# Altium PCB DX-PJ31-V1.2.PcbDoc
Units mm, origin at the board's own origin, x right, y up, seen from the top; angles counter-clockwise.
Board outline 28 x 32 mm, 2 copper layers (Top, Bottom), stack 0.324 mm thick; 82 components, 60 nets, 437 pads, 151 vias.
Unrouted connection lines stored in the file: 298.
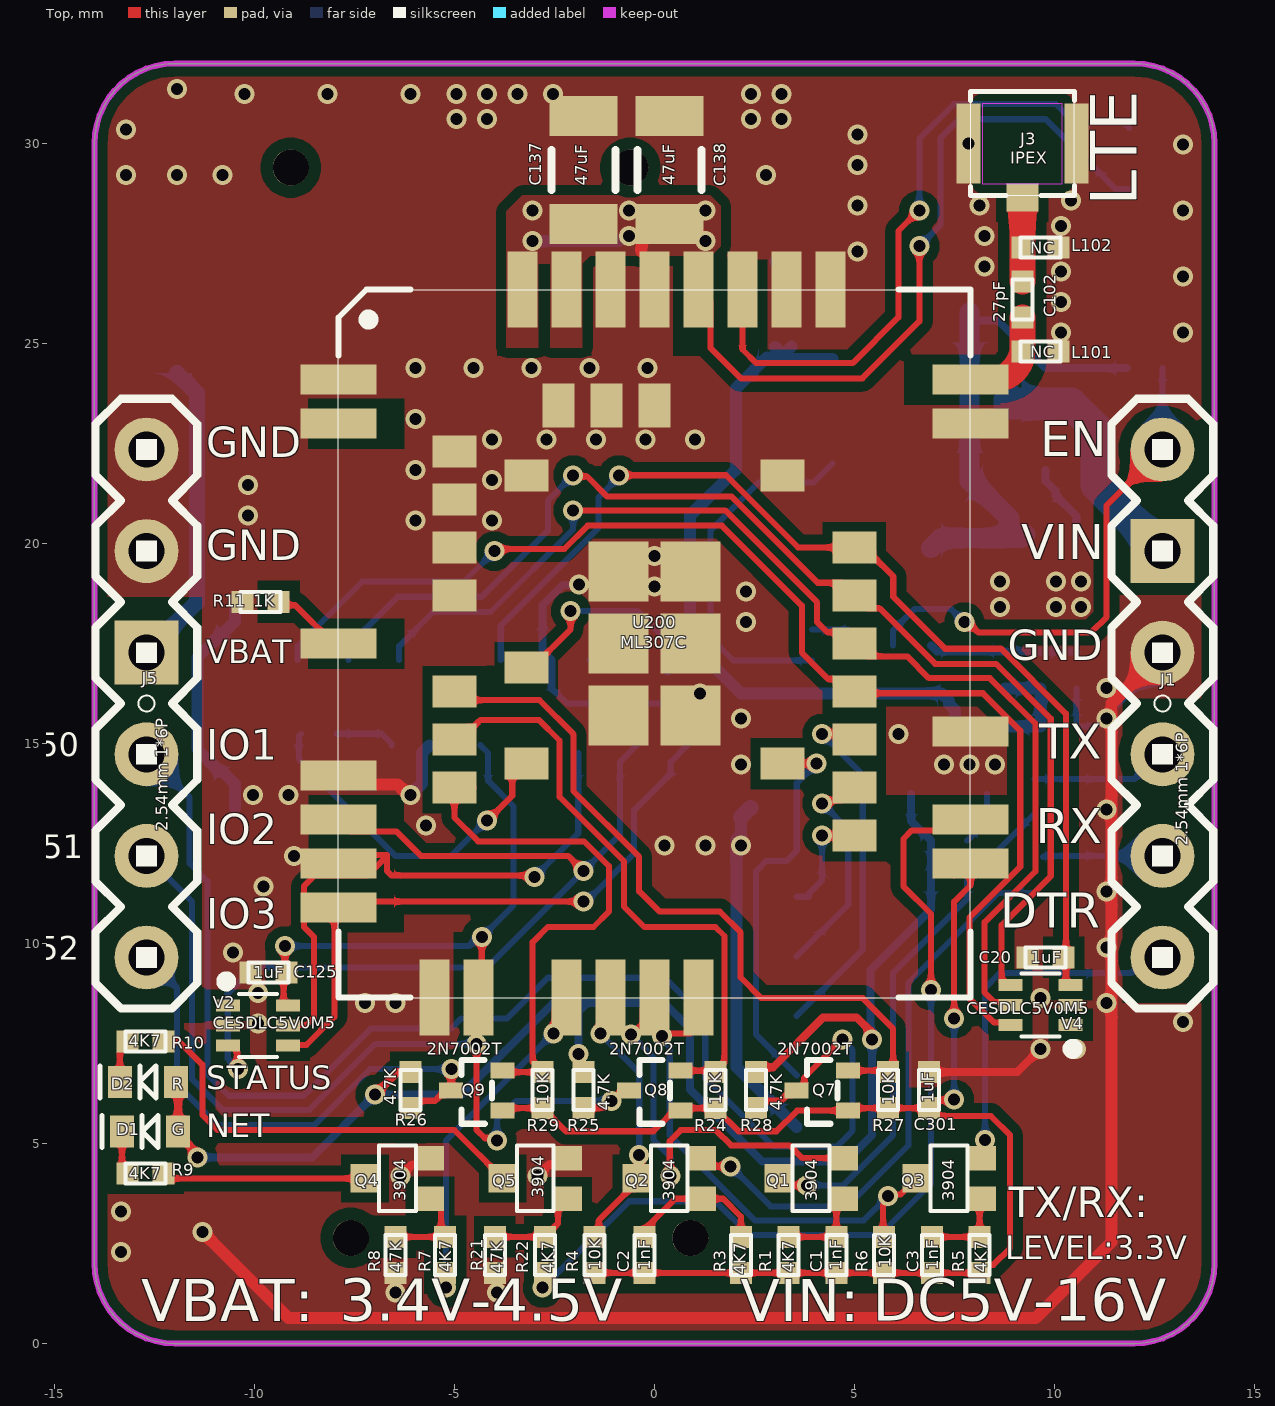
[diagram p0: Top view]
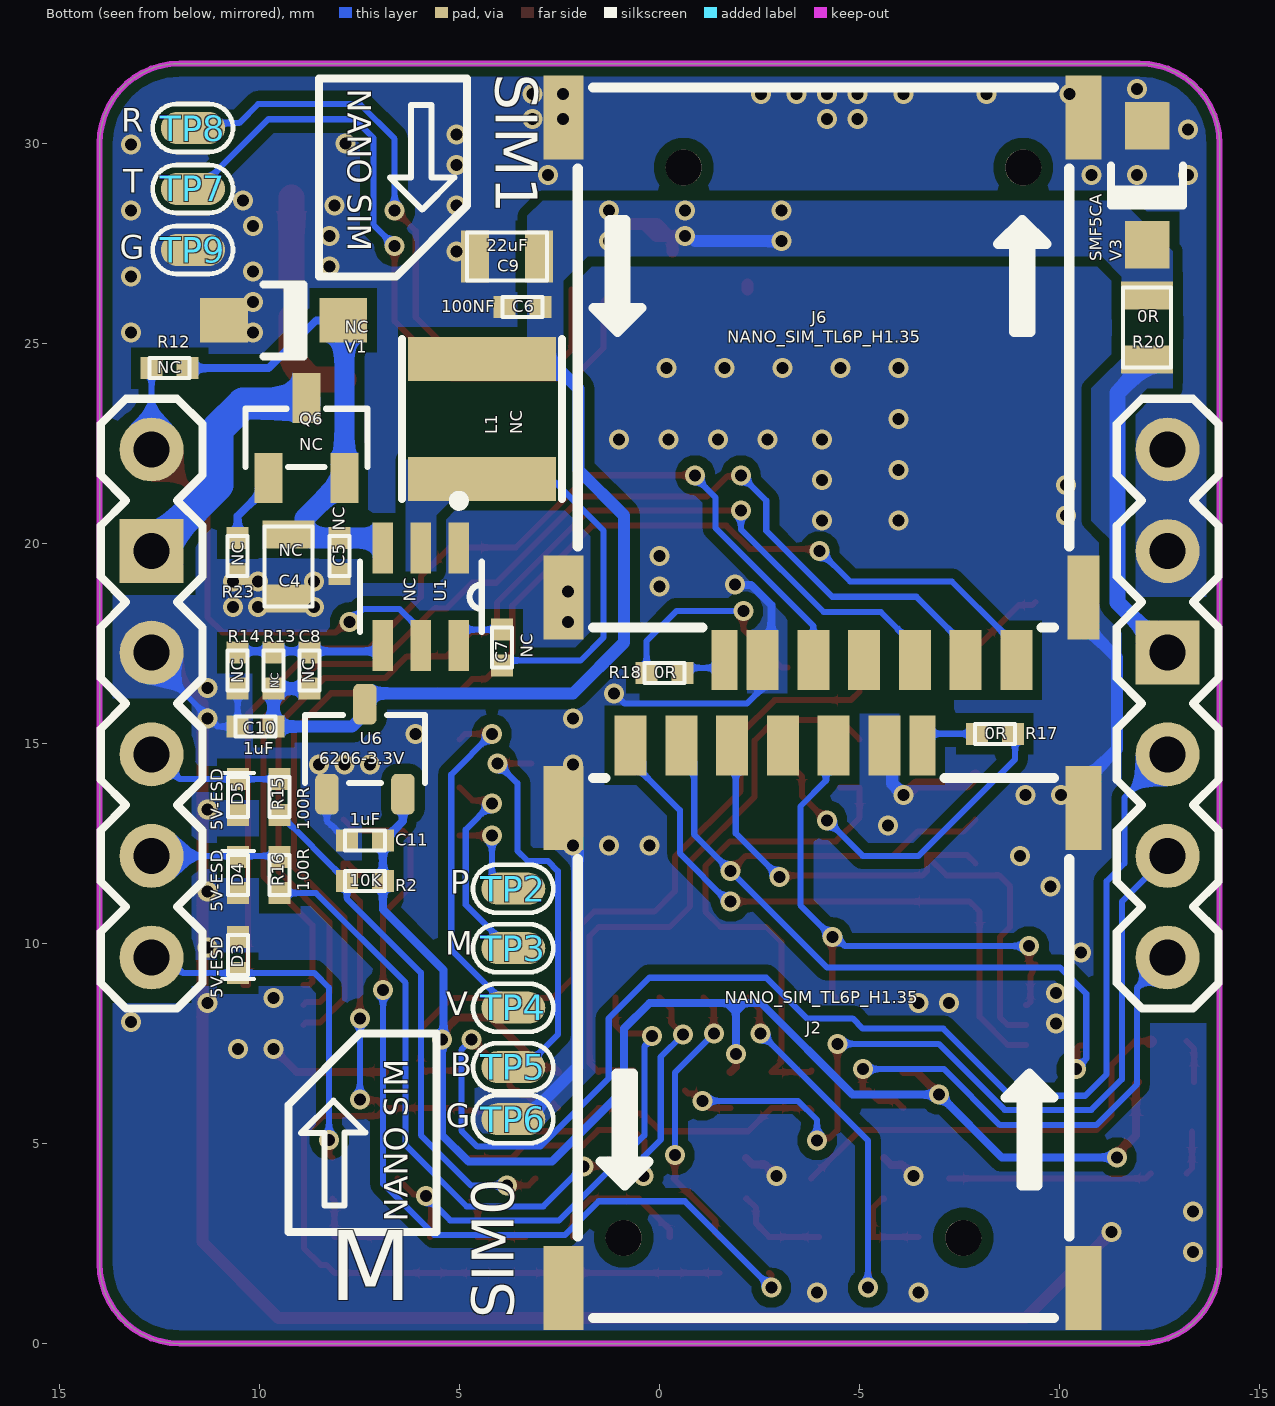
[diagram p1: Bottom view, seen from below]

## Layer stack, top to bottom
Solder Mask Top: solder mask 0.0102, Solder Resist, Dk 3.5
Top: signal copper 0.035
Dielectric1: dielectric 0.254, FR-4, Dk 4.8
Bottom: signal copper 0.035
Solder Mask Bottom: solder mask 0.0102, Solder Resist, Dk 3.5

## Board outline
-14,2 -14,30 cw(c-12,30) -12,32 12,32 cw(c12,30) 14,30 14,2 cw(c12,2) 12,0 -12,0 cw(c-12,2)

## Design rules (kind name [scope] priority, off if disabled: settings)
Clearance [All] p1: gap=0.2 ignorepadtopadclearanceinfootprint=TRUE except(0: Arc-Hole Track-Hole SMDPad-Hole THPad-Hole Via-Hole Fill-Hole Poly-Hole Region-Hole Text-Hole; 0.25: Arc-Fill Arc-Poly Arc-Region Track-Fill Track-Poly Track-Region SMDPad-Fill SMDPad-Poly SMDPad-Region Via-Fill Via-Poly Via-Region Fill-Fill Fill-Poly Fill-Region Poly-Poly Poly-Region Region-Region; 0.3: THPad-Fill THPad-Poly THPad-Region)
ComponentClearance "ComponentClearance - Default - DEFAULT" [All] p1: gap=0.152 collisioncheckmode=3 verticalgap=0.254 showdistances=FALSE
FanoutControl Fanout_SOIC [IsSOIC] p1: bgadir=Out bgaviamode=Centered fanoutstyle=Auto fanoutdirection=Alternating viagrid=0.025 // Fanout_SOIC (Default Rule)
FanoutControl Fanout_Small [(CompPinCount < 5)] p2: bgadir=Out bgaviamode=Centered fanoutstyle=Auto fanoutdirection=OutThenIn viagrid=0.025 // Fanout_Small (Default Rule)
FanoutControl Fanout_LCC [IsLCC] p3: bgadir=Out bgaviamode=Centered fanoutstyle=Auto fanoutdirection=Alternating viagrid=0.025 // Fanout_LCC (Default Rule)
FanoutControl Fanout_BGA [IsBGA] p4: bgadir=Out bgaviamode=Centered fanoutstyle=Auto fanoutdirection=Alternating viagrid=0.025 // Fanout_BGA (Default Rule)
HoleToHoleClearance "HoleToHoleClearance - Default - DEFAULT" [All] p1: gap=0.152 allowstackedmicrovias=TRUE
Length "Default Length" [All] p1: maxlimit=1270 minlimit=0
MaxMinImpedance "Default Impedance" [All] p1: minimum=50.00 maximum=150.0
MinimumSolderMaskSliver [All] p1: minsoldermaskwidth=0.2
ParallelSegment "Default Parallel Segment Adjasent" [All] p1: limit=25.4 gap=5.08
ParallelSegment "Default Parallel Segment Same Layer" [All] p2: limit=25.4 gap=5.08
PlaneClearance "PlaneClearance - FootPrint 'LUOSI2MM-P'" [HasFootprint('LUOSI2MM-P')] p1: clearance=1.075 // PAD - Power Plane Clearance
PlaneConnect "PlaneConnect - FootPrint 'LUOSI2MM-NP'" [All] p1: planeconnectstyle=Direct reliefexpansion=1.675 reliefentries=4 reliefconductorwidth=0.55 reliefairgap=0
PolygonConnect "PolygonConnect - FootPrint 'LUOSI2MM-NP'" [All] p1: connectstyle=Direct reliefconductorwidth=0.55 reliefentries=4 polygonreliefangle="45 Angle" airgapwidth=0.254
RoutingLayers "RoutingLayers - Default - DEFAULT" [All] p1: top layer_v5=TRUE bottom layer_v5=TRUE
RoutingPriority "RoutingPriority - Default - DEFAULT" [All] p1: routingpriority=3
RoutingTopology "Default Routing Topology" [All] p1: topology=Shortest
RoutingVias "RoutingVias - Default - DEFAULT" [All] p1: holewidth=0.3 width=0.5 viastyle="Through Hole" minholewidth=0.25 minwidth=0.45 maxholewidth=1 maxwidth=2
SMDToCorner "SMDToCorner - Default - DEFAULT" [All] p1: distance=60000
SilkToSilkClearance [All] p1: silktosilkclearance=0
SilkToSolderMaskClearance [IsPad] p1: minsilkscreentomaskgap=0 clearancetoexposedcopper=TRUE
SolderMaskExpansion [All] p1: expansion=0.102 istentingtop=FALSE
Width "Default Width" [All] p1: maxlimit=1 minlimit=0.15 preferedwidth=0.15
16 further rules are at their usual default settings.

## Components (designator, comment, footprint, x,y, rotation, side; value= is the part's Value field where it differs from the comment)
C1 "1nF" SMD0402 4.547,2.217 r270 top
C2 "1nF" SMD0402 -0.254,2.217 r270 top
C3 "1nF" SMD0402 6.934,2.217 r270 top
C4 "NC" SMD0805 9.271,19.431 r90 bottom value=10uF
C5 "NC" SMD0402 8.001,19.685 r90 bottom value=0.1uF
C6 "100NF" SMD0402 3.429,25.908 r180 bottom value=1uF
C7 "NC" SMD0402 3.937,17.399 r90 bottom value=0.1uF
C8 "NC" SMD0402 8.758,16.822 r270 bottom value=10pF
C9 "22uF" SMD0805 3.81,27.178 r180 bottom
C10 "1uF" SMD0402 10.096,15.425 r180 bottom
C11 "1uF" SMD0402 7.366,12.573 r180 bottom
C20 "1uF" SMD0402 9.779,9.652 r0 top
C102 "27pF" SMD0402 9.2,26.1 r90 top
C125 "1uF" SMD0402 -9.652,9.271 r0 top
C137 "47uF" C1206L -1.778,29.337 r270 top
C138 "47uF" C1206L 0.381,29.337 r270 top
C301 "1uF" SMD0402 6.858,6.334 r270 top
D1 "G" LED_0603 -12.611,5.3 r180 top
D2 "R" LED_0603 -12.665,6.54 r180 top value=G
D3 "5V-ESD" SMD0402_ESD_TVS 10.541,9.71 r90 bottom value="5V 10P"
D4 "5V-ESD" SMD0402_ESD_TVS 10.541,11.713 r270 bottom value="5V 10P"
D5 "5V-ESD" SMD0402_ESD_TVS 10.541,13.658 r270 bottom value="5V 10P"
J1 "2.54mm 1*6P" 254-6#1 12.7,16 r270 top locked value="2.54mm 1*6P直针/黄色"
J2 "NANO_SIM_TL6P_H1.35" nanosim_#1 -4.619,8.191 r180 bottom locked value="NANO SIM TL6P H1.35"
J3 "IPEX" IPEX 9.2,30 r270 top
J5 "2.54mm 1*6P" 254-6#2 -12.7,16 r270 top locked value="2.54mm 1*6P直针/黄色"
J6 "NANO_SIM_TL6P_H1.35" nanosim_#2 -3.577,23.849 r0 bottom locked value="NANO SIM TL6P H1.35"
L1 "NC" WPN4020H 4.445,23.114 r90 bottom value=WPN4020H2R2MT
L101 "NC" SMD0402 9.65,24.8 r0 top
L102 "NC" SMD0402 9.65,27.4 r0 top
Q1 "3904" EMT3 3.916,4.127 r90 top value=3904/SOT-523
Q2 "3904" EMT3 0.368,4.127 r90 top value=3904/SOT-523
Q3 "3904" EMT3 7.364,4.127 r90 top value=3904/SOT-523
Q4 "3904" EMT3 -6.428,4.127 r90 top value=3904/SOT-523
Q5 "3904" EMT3 -2.98,4.127 r90 top value=3904/SOT-523
Q6 "NC" SOT-23-3_L2.9-W1.3-P1.90-LS2.4-BR 8.829,22.644 r270 bottom
Q7 "2N7002T" SC-75-3_L1.6-W0.8-P1.00-LS1.7-BR 4.199,6.323 r0 top
Q8 "2N7002T" SC-75-3_L1.6-W0.8-P1.00-LS1.7-BR 0.004,6.323 r0 top
Q9 "2N7002T" SC-75-3_L1.6-W0.8-P1.00-LS1.7-BR -4.445,6.323 r0 top
R1 "4K7" SMD0402 3.353,2.217 r90 top
R2 "10K" SMD0402 7.366,11.557 r180 bottom
R3 "4K7" SMD0402 2.159,2.217 r90 top
R4 "10K" SMD0402 -1.499,2.217 r270 top
R5 "4K7" SMD0402 8.128,2.217 r90 top
R6 "10K" SMD0402 5.74,2.217 r270 top
R7 "4K7" SMD0402 -5.232,2.217 r270 top
R8 "47K" SMD0402 -6.477,2.217 r90 top
R9 "4K7" SMD0402 -12.73,4.254 r180 top value=2K2
R10 "4K7" SMD0402 -12.73,7.556 r180 top value=2K2
R11 "1K" SMD0402 -9.848,18.542 r180 top
R12 "NC" SMD0402 12.25,24.384 r0 bottom value=10K
R13 "NC" SMD0402 9.652,16.822 r90 bottom value=41.2K1%
R14 "NC" SMD0402 10.546,16.822 r270 bottom value=10K1%
R15 "100R" SMD0402 9.496,13.658 r270 bottom value=1K
R16 "100R" SMD0402 9.496,11.713 r270 bottom value=1K
R17 "0R" SMD0402 -8.382,15.24 r0 bottom value=1K
R18 "0R" SMD0402 -0.127,16.764 r180 bottom value=1K
R20 "0R" SMD0805 -12.192,25.4 r90 bottom value=1K
R21 "47K" SMD0402 -3.988,2.217 r90 top
R22 "4K7" SMD0402 -2.743,2.217 r270 top
R23 "NC" SMD0402 10.546,19.685 r270 bottom value=1K
R24 "10K" SMD0402 1.524,6.334 r90 top
R25 "4.7K" SMD0402 -1.778,6.334 r270 top value=10K
R26 "4.7K" SMD0402 -6.096,6.334 r270 top value=10K
R27 "10K" SMD0402 5.842,6.334 r270 top value=4K7
R28 "4.7K" SMD0402 2.54,6.334 r90 top value=4K7
R29 "10K" SMD0402 -2.794,6.334 r90 top value=4K7
TP2 "TP2" TP-0.8X1.6 3.656,11.369 r0 bottom value=NC
TP3 "TP3" TP-0.8X1.6 3.656,9.882 r0 bottom value=NC
TP4 "TP4" TP-0.8X1.6 3.656,8.395 r0 bottom value=NC
TP5 "TP5" TP-0.8X1.6 3.656,6.908 r0 bottom value=NC
TP6 "TP6" TP-0.8X1.6 3.656,5.608 r0 bottom value=NC
TP7 "TP7" TP-0.8X1.6 11.665,28.864 r0 bottom value=NC
TP8 "TP8" TP-0.8X1.6 11.665,30.388 r0 bottom value=NC
TP9 "TP9" TP-0.8X1.6 11.665,27.34 r0 bottom value=NC
U1 "NC" DDC0006A_L 5.969,18.669 r270 bottom value=TPS563201DDCR
U6 "6206-3.3V" SOT23-3P95_280X110L60X40L 7.366,14.859 r180 bottom
U200 "ML307C" L511-1 0,17.5 r0 top locked value=L511
V1 "NC" SOD123FL 9.398,25.581 r0 bottom value=SMF18CA/SOD-123FL
V2 "CESDLC5V0M5" SOT-563_L1.6-W1.2-P0.50-LS1.6-BR -9.906,7.954 r180 top
V3 "SMF5CA" SOD123FL -12.192,28.956 r90 bottom value=SMF18CA/SOD-123FL
V4 "CESDLC5V0M5" SOT-563_L1.6-W1.2-P0.50-LS1.6-BR 9.652,8.466 r0 top

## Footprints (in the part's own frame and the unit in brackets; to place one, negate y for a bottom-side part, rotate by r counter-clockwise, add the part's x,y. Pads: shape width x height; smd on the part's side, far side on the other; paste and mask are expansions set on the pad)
254-6#1 [mm]
  round 1.6 hole 0.9: 1(6.35,0) 2(3.81,0) 3(1.27,0) 4(-1.27,0) 6(-6.35,0)
  rect 1.6x1.6 hole 0.9: 5(-3.81,0)
  silkscreen extent -7.62,-1.27 7.62,1.27
254-6#2 [mm]
  round 1.6 hole 0.9: 1(6.35,0) 2(3.81,0) 3(1.27,0) 5(-3.81,0) 6(-6.35,0)
  rect 1.6x1.6 hole 0.9: 4(-1.27,0)
  silkscreen extent -7.62,-1.27 7.62,1.27
C1206L [mm]
  rect 1x1.7 smd: 1(-1.35,0) 2(1.35,0)
  silkscreen extent -0.5,-0.8 0.5,0.8
DDC0006A_L [mil]
  rect 50x20 smd mask+2.01: 1(-47.99,37.4) 2(-47.99,0) 3(-47.99,-37.4) 4(47.99,-37.4) 5(47.99,0) 6(47.99,37.4)
  silkscreen extent -99,-60 34,60
EMT3 [mil]
  rect 24x28 smd: 1(20,-32) 2(-20,-32)
  rect 28x28 smd: 3(0,32)
  silkscreen extent -32,-18 32,18
IPEX [mm]
  rect 2x0.6 smd mask+0.05: 1(0,1.35) 2(0,-1.35)
  rect 0.7x0.8 smd mask+0.025: 3(1.35,0)
  silkscreen extent -1.3,-1.3 1.3,1.3
L511-1 [mm]
  rect 1.9x0.75 on Top Solder: 1(-7.9,-6.6) 1(-7.9,-5.5) 1(-7.9,-4.4) 1(-7.9,-3.3) 1(-7.9,0) 1(-7.9,5.5) 1(-7.9,6.6) 1(7.9,-5.5) 1(7.9,-4.4) 1(7.9,-2.2) 1(7.9,5.5) 1(7.9,6.6)
  rect 1.9x0.75 smd: 1(-7.9,6.6) 2(-7.9,5.5) 7(-7.9,0) 10(-7.9,-3.3) 11(-7.9,-4.4) 12(-7.9,-5.5) 13(-7.9,-6.6) 24(7.9,-5.5) 25(7.9,-4.4) 27(7.9,-2.2) 34(7.9,5.5) 35(7.9,6.6)
  rect 0.75x1.9 on Top Solder: 1(-5.5,-8.85) 1(-4.4,-8.85) 1(-3.3,8.85) 1(-2.2,-8.85) 1(-2.2,8.85) 1(-1.1,-8.85) 1(-1.1,8.85) 1(0,-8.85) 1(0,8.85) 1(1.1,-8.85) 1(3.3,8.85) 1(4.4,8.85) 40(2.2,8.85) 41(1.1,8.85)
  rect 1.9x0.75 on Top Overlay: 2(-7.9,-2.2) 2(-7.9,-1.1) 2(-7.9,1.1) 2(-7.9,2.2) 2(-7.9,3.3) 2(-7.9,4.4) 2(-7.9,4.4) 14(7.9,-6.6) 14(7.9,-3.3) 14(7.9,-1.1) 14(7.9,0) 14(7.9,1.1) 14(7.9,2.2) 14(7.9,3.3) 14(7.9,4.4)
  round 0 all layers, no hole: 3(0,0) 4(0,0) 5(0,0) 6(0,0) 8(0,0) 9(0,0) 15(0,0) 20(0,0) 21(0,0) 22(0,0) 23(0,0) 25(0,0) 26(0,0) 28(0,0) 29(0,0) 31(0,0) 32(0,0) 33(0,0) 38(0,0) 39(0,0) 44(0,0) 49(0,0) 50(0,0) 51(0,0) 52(0,0) 53(0,0) 54(0,0) 55(0,0) 56(0,0) 57(0,0) 58(0,0) 62(0,0) 63(0,0) 64(0,0) 65(0,0) 66(0,0) 67(0,0) 68(0,0) 69(0,0) 74(0,0) 75(0,0) 76(0,0) 77(0,0) 78(0,0) 79(0,0) 80(0,0) 81(0,0) 83(0,0) 84(0,0) 85(0,0) 86(0,0) 87(0,0) 96(0,0) 97(0,0) 98(0,0) 99(0,0) 100(0,0) 101(0,0) 102(0,0) 103(0,0) 104(0,0) 105(0,0) 106(0,0) 107(0,0) 108(0,0) 109(0,0)
  rect 0.75x1.9 on Top Overlay: 14(-5.5,8.85) 14(-4.4,8.85) 14(-3.3,-8.85) 14(2.2,-8.85) 14(3.3,-8.85) 14(4.4,-8.85) 14(5.5,-8.85) 14(5.5,8.85)
  rect 0.75x1.9 smd: 14(-4.4,-8.85) 16(-2.2,-8.85) 17(-1.1,-8.85) 18(0,-8.85) 19(1.1,-8.85) 36(4.4,8.85) 37(3.3,8.85) 38(2.2,8.85) 39(1.1,8.85) 40(0,8.85) 41(-1.1,8.85) 42(-2.2,8.85) 43(-3.3,8.85) 95(-5.5,-8.85)
  rect 1.1x0.8 on Top Overlay: 45(-5,-6) 45(-5,-4.8) 45(-5,0) 45(-5,6) 45(5,-6) 45(5,3.6) 45(5,4.8) 45(5,6) 70(-3.2,1.8) 70(3.2,-0.6) 70(3.2,1.8) 71(-3.2,-4.2) 71(-3.2,-1.8) 71(-3.2,0.6) 71(-3.2,3) 71(3.2,-4.2) 71(3.2,-1.8) 71(3.2,0.6) 71(3.2,3)
  rect 1.1x0.8 on Top Solder: 45(-5,-3.6) 45(-5,-2.4) 45(-5,-1.2) 45(-5,1.2) 45(-5,2.4) 45(-5,3.6) 45(-5,4.8) 45(-3.2,-3) 45(-3.2,-0.6) 45(-3.2,4.2) 45(3.2,-3) 45(3.2,4.2) 45(5,-4.8) 45(5,-3.6) 45(5,-2.4) 45(5,-1.2) 45(5,0) 45(5,1.2) 45(5,2.4)
  rect 1.1x0.8 smd: 45(-5,4.8) 46(-5,3.6) 47(-5,2.4) 48(-5,1.2) 50(-5,-1.2) 51(-5,-2.4) 52(-5,-3.6) 59(5,-4.8) 60(5,-3.6) 61(5,-2.4) 62(5,-1.2) 63(5,0) 64(5,1.2) 65(5,2.4) 73(-3.2,4.2) 77(-3.2,-0.6) 79(-3.2,-3) 82(3.2,-3) 88(3.2,4.2)
  rect 0.8x1.1 on Top Overlay: 45(-3.6,-6.05) 45(-3.6,5.95) 70(0,-6.05) 70(0,-4.05) 70(2.4,-6.05) 70(2.4,5.95) 71(-1.2,-6.05) 71(-1.2,-4.05) 71(1.2,-6.05) 71(1.2,-4.05) 71(1.2,5.95) 72(-2.4,-6.05) 72(3.6,-6.05) 72(3.6,5.95)
  rect 0.8x1.1 on Top Solder: 45(-2.4,5.95) 45(-1.2,5.95) 45(0,5.95)
  rect 0.8x1.1 smd: 70(0,5.95) 71(-1.2,5.95) 72(-2.4,5.95)
  rect 1.5x1.5 on Top Solder: 89(-0.9,-1.8) 89(-0.9,0) 89(-0.9,1.8) 89(0.9,-1.8) 89(0.9,0) 89(0.9,1.8)
  rect 1.5x1.5 smd: 89(-0.9,1.8) 90(-0.9,0) 91(-0.9,-1.8) 92(0.9,-1.8) 93(0.9,0) 94(0.9,1.8)
  silkscreen extent -7.9,-8.85 7.9,8.85
LED_0603 [mm]
  rect 0.6x0.8 smd: 1(-0.7,0) 2(0.7,0)
  silkscreen extent -0.2,-0.4 1.2,0.4
nanosim_#1 [mm]
  rect 1x2.1 smd: 8(-7.016,5.2) 9(-7.016,-6.8)
  rect 0.9x2.1 smd: 8(5.974,5.2) 9(5.974,-6.8)
  rect 0.8x1.5 smd: C1(-0.266,6.765) C2(-2.806,6.765) C3(-5.346,6.765) C5(1.004,6.765) C6(-1.536,6.765) C7(-4.076,6.765)
  rect 0.65x1.5 smd: CD(1.954,6.765)
  round 0.9 hole 0.9 unplated: ""(-5.516,-5.551) ""(2.974,-5.551)
  silkscreen extent -6.67,-7.55 5.62,5.95
nanosim_#2 [mm]
  rect 0.8x2.1 smd: 8(-7.016,5.2)
  rect 1x2.1 smd: 8(5.974,5.2) 9(5.974,-6.8)
  rect 0.9x2.1 smd: 9(-7.016,-6.8)
  rect 0.8x1.5 smd: C1(-0.266,6.765) C2(-2.806,6.765) C3(-5.346,6.765) C5(1.004,6.765) C6(-1.536,6.765) C7(-4.076,6.765)
  rect 0.65x1.5 smd: CD(1.954,6.765)
  round 0.9 hole 0.9 unplated: ""(-5.516,-5.551) ""(2.974,-5.551)
  silkscreen extent -6.67,-7.55 5.62,5.95
SC-75-3_L1.6-W0.8-P1.00-LS1.7-BR [mm]
  rect 0.6x0.4 smd paste+0.051: 1(0.643,-0.5) 2(0.643,0.5) 3(-0.643,0)
  silkscreen extent -0.38,-0.83 0.38,0.76
SMD0402 [mm]
  rect 0.55x0.55 smd: 1(-0.45,0) 2(0.45,0)
  silkscreen extent -0.5,-0.25 0.5,0.25
SMD0402_ESD_TVS [mm]
  rect 0.55x0.55 smd: 1(-0.45,0) 2(0.45,0)
  silkscreen extent -0.6,-0.4 0.5,0.4
SMD0805 [mm]
  rect 0.7x1.3 smd: 1(-0.8,0) 2(0.8,0)
  silkscreen extent -1,-0.6 1,0.6
SOD123FL [mm]
  rect 1.19x1.12 smd: 1(-1.49,0) 2(1.49,0)
  silkscreen extent -0.5,-0.9 0.5,0.9
SOT23-3P95_280X110L60X40L [mm]
  rrect50% 0.589x1.02 smd: 1(-0.95,-1.125) 2(0.95,-1.125) 3(0,1.125)
  silkscreen extent -1.5,-0.85 1.5,0.85
SOT-23-3_L2.9-W1.3-P1.90-LS2.4-BR [mm]
  rect 1.25x0.7 smd: 1(1,-0.95) 2(1,0.95) 3(-1,0)
  silkscreen extent -0.73,-1.53 0.73,1.53
SOT-563_L1.6-W1.2-P0.50-LS1.6-BR [mm]
  rect 0.6x0.3 smd: 1(0.75,-0.5) 2(0.75,0) 3(0.75,0.5) 4(-0.75,0.5) 5(-0.75,0) 6(-0.75,-0.5)
  silkscreen extent -0.48,-1.22 0.92,0.79
TP-0.8X1.6 [mm]
  oval 1.6x0.8 smd paste-0.8 mask+0.05: 1(0,0)
  silkscreen extent -1,-0.6 1.01,0.6
WPN4020H [mm]
  rect 1.1x3.7 smd: 1(-1.5,0) 2(1.5,0)
  silkscreen extent -2,-2 2,2

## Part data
C1 C2 C3 C5 C6 C7 C8 C10 C11 C20 C102 C125 C301: library part CAP-0402, PART NUMBER=0402ZG104Z, Tolerance=+/-5%
C4 C9 C137 C138: library part CAP-0805
D1 D2: library part LED_0603
D3 D4 D5 V1 V3: library part ESD-TVS-0402
J1 J5: library part 254-6
J2 J6: JLCPCB_Part_Class="Extended Part", Manufacturer_Part="NANO SIM TL6P H1.35"
J3: library part UFLR_0
L1: library part INCT_1_L5
L101 L102: library part IND-0402
Q1 Q2 Q3 Q4 Q5: library part DTC123JETL
Q6: library part MOS-P, "1:G 2:D 3:S"
R1 R2 R3 R4 R5 R6 R7 R8 R9 R10 R11 R12 R13 R14 R15 R16 R17 R18 R20 R21 R22 R23 R24 R25 R26 R27 R28 R29: library part RES-0402
TP2 TP3 TP4 TP5 TP6 TP7 TP8 TP9: library part TP_C150A, "test point on module"
U1: library part TPS563201DDCR, Mfr_Name="Texas Instruments"
U6: library part LDO
U200: library part L511_BLGA
V2 V4: Breakdown_Voltage=6.2V, JLCPCB_Part_Class="Extended Part", Maximum_Clamping_Voltage=13V, Peak_Pulse_Current_(Ipp)@10/1000us=2.5A, Reverse_Stand_Off_Voltage_(Vrwm)=5V

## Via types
v1: diameter 0.5, hole 0.3, Top to Bottom, tented both sides, 151 vias

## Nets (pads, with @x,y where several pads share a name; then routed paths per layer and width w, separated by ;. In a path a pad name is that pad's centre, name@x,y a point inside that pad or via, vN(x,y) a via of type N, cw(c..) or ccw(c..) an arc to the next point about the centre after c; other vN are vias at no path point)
ANT_RF: C102.1 L101.1 U200.35 | length 2.5
  Top w0.646: U200.35 8.5,24.1 ccw(c8.5,24.8) L101.1 C102.1
ANTRF1: C102.2 J3.3 L102.1 | length 2.1
  Top w0.646: C102.2 L102.1 J3.3
BAT: J5.4 R20.1 | length 7.7
  Bottom w0.4: J5.4 -11.443,18.527 -11.443,23.762 R20.1@-11.938,24.257
CD1: J2.CD R17.2 | length 1.5
  Bottom w0.152: R17.2@-7.932,15.245 -6.822,15.245 -6.573,14.996 J2.CD
CD2: J6.CD R18.2 | length 1.1
  Bottom w0.152: J6.CD -1.429,16.891 R18.2@-0.577,16.891
DBG_RX: TP8.1 U200.38 | length 16.5
  Top w0.152: U200.38@2.2,26.35 2.2,24.851 2.54,24.511 4.953,24.511 6.096,25.654 6.096,27.813 v1@6.604,28.321
  Bottom w0.152: v1(6.622,28.321) 6.622,30.117 7.493,30.988 10.033,30.988 10.509,30.512 11.741,30.512 TP8.1@11.865,30.388
DBG_TX: TP7.1 U200.39 | length 18.1
  Top w0.152: U200.39@1.1,26.35 1.399,26.051 1.399,24.89 2.159,24.13 5.197,24.13 6.622,25.555 v1(6.622,27.432)
  Bottom w0.152: v1(6.622,27.432) 7.148,27.958 7.148,30.135 7.62,30.607 9.779,30.607 11.522,28.864 TP7.1@11.865,28.864
DTR: D3.1 J1.1 Q3.1 | length 9
  Top w0.152: Q3.1 8.264,4.722 v1(8.264,5.089)
  Bottom w0.152: v1(8.264,5.089) 8.264,8.899 8.625,9.26 D3.1 11.918,9.26 12.308,9.65 J1.1
GND: C4.1 C5.1 C6.1 C9.1 C10.1 C11.1 C20.1 C125.1 C137.1 C138.1 C301.1 D3.2 D4.2 D5.2 J1.4 J2.8 J2.9 J2.C5 J3.1 J3.2 J5.5 J5.6 J6.8 J6.9 J6.C5 L101.2 L102.2 Q4.1 Q5.1 R8.1 R11.2 R14.2 R21.1 R23.2 TP6.1 TP9.1 U1.1 U6.1 U200.1@-7.9,24.1 U200.10 U200.27 U200.34 U200.36 U200.37 U200.40@0,26.35 U200.41@-1.1,26.35 U200.45@-5,22.3 U200.46 U200.47 U200.48 U200.70@0,23.45 U200.71@-1.2,23.45 U200.72@-2.4,23.45 U200.73 U200.88 U200.89@-0.9,19.3 U200.90 U200.91 U200.92 U200.93 U200.94 U200.95 V1.2 V2.2 V3.2 V4.2 | length 75.7
  Top w0.15: U200.94 U200.94@0.9,19.4
  Top w0.2: v1(-6.35,4.191) -6.074,4.467 -5.783,4.467 Q4.1 ; v1(-2.921,4.191) -2.636,4.476 -2.327,4.476 Q5.1 ; C301.1 9.07,6.784 v1(9.652,7.366)
  Top w0.3: v1(-11.303,2.794) -9.144,0.635 9.525,0.635 11.43,2.54 11.43,16 J1.4 ; U200.10 -7.675,13.975 -6.42,13.975 -6.199,13.754 -6.134,13.754 v1(-6.096,13.716)
  Bottom w0.15: J6.C5@-2.573,16.383 -2.192,16.002 0.88,16.002 1.134,16.256 v1(1.143,16.256) ; C11.1 8.199,12.956 8.212,12.956 8.316,13.059 U6.1 ; R14.2 C10.1 11.045,15.425 J1.4@12.695,17.074
  Bottom w0.2: J6.C5@-2.573,16.383 J6.C5 -2.794,17.306 -2.794,18.46 -2.29,18.964 -1.903,18.964 v1(-1.887,18.979)
  Bottom w0.3: J2.8@-10.493,13.391 -10.493,13.991 -10.793,14.291 -10.862,14.291 -11.43,14.859 -11.43,17.145 -10.825,17.75 -10.793,17.75 -10.493,18.05 J6.8@-10.493,18.65 ; v1(-6.096,13.716) -6.096,13.719 -5.813,14.002 -5.813,14.766 J2.C5 ; v1(2.159,12.446) J2.8@2.159,13.153 ; J2.8@2.159,12.722 2.047,12.61 2.047,7.261 2.047,6.916 TP6.1@3.556,5.408 ; J2.8@2.194,12.446 J2.8@2.248,12.392
  Bottom w0.4: J2.8@2.159,13.153 J2.8@2.397,13.391
  other v1: -6.477,1.27 -3.937,1.27 -13.335,2.286 -13.335,3.302 10.541,7.366 -9.906,8.001 13.208,8.043 -7.239,8.509 -6.477,8.509 11.303,8.509 9.652,8.636 -9.906,8.763 -10.541,9.779 11.303,9.906 11.303,11.303 -9.779,11.43 -9.017,12.192 0.254,12.446 1.27,12.446 -5.715,12.954 11.303,13.345 -10.033,13.716 -9.144,13.716 2.159,14.478 7.239,14.478 7.874,14.478 8.509,14.478 6.096,15.24 2.159,15.621 11.303,15.621 11.303,16.383 2.286,18.034 8.636,18.415 10.033,18.415 10.668,18.415 2.286,18.796 0,18.923 8.636,19.05 10.033,19.05 10.668,19.05 0,19.685 -5.969,20.574 -4.064,20.574 -10.16,20.701 -10.16,21.463 -4.064,21.59 -5.969,21.844 -4.064,22.606 -2.699,22.606 -1.46,22.606 -0.222,22.606 1.016,22.606 -5.969,23.114 -5.969,24.384 -4.521,24.384 -3.073,24.384 -1.626,24.384 -0.178,24.384 10.16,25.273 13.208,25.273 10.16,26.035 13.208,26.67 10.16,26.797 8.255,26.924 5.08,27.305 8.255,27.686 10.16,27.94 13.208,28.321 5.08,28.448 8.128,28.448 10.414,28.575 -13.208,29.21 -11.938,29.21 -10.795,29.21 2.794,29.21 5.08,29.464 13.208,29.972 7.85,30 5.08,30.226 -13.208,30.353 -4.953,30.607 -4.191,30.607 2.413,30.607 3.175,30.607 -10.245,31.242 -8.17,31.242 -6.096,31.242 -4.953,31.242 -4.191,31.242 -3.429,31.242 -2.54,31.242 2.413,31.242 3.175,31.242 -11.938,31.369
IO1: J5.3 Q7.3 R28.1 | length 34.7
  Top w0.152: J5.3 J5.3@-12.311,14.73 ; R28.1 2.725,6.069 3.16,6.069 3.29,6.199 3.432,6.199 Q7.3 3.623,6.323 3.747,6.447 3.747,6.651 v1(4.699,7.603)
  Bottom w0.152: J5.3 -11.624,13.654 -11.624,12.005 -11.176,11.557 -11.176,6.731 -10.639,6.194 -8.772,6.194 -7.093,7.874 -5.08,7.874 -4.826,8.128 -3.683,8.128 -2.667,9.144 0.254,9.144 1.27,8.128 1.27,6.637 2.959,4.948 2.977,4.948 ; 2.977,4.923 4.554,4.923 4.953,5.323 4.953,7.34 4.699,7.594 v1(4.699,7.603)
IO2: J5.2 Q8.3 R25.2 | length 21.8
  Top w0.152: v1(-4.445,7.493) -4.445,5.334 -4.25,5.139 -3.996,5.139 v1(-3.937,5.08) ; R25.2 -1.253,5.884 v1(-1.071,6.066) -0.889,6.249 -0.713,6.249 Q8.3
  Bottom w0.152: J5.2 -11.557,11.047 -11.557,6.604 -10.795,5.842 -8.626,5.842 -6.975,7.493 v1(-4.445,7.493) ; v1(-3.937,5.08) -3.937,5.588 -3.459,6.066 v1(-1.071,6.066)
IO3: J5.1 Q9.3 R26.2 | length 13.1
  Top w0.152: R26.2 -5.91,6.07 -5.482,6.07 -5.23,6.323 Q9.3 -5.08,6.331 v1(-5.08,6.858)
  Bottom w0.152: J5.1 -11.938,8.888 -11.938,6.477 -10.922,5.461 -8.509,5.461 -7.112,6.858 v1(-5.08,6.858)
LDO3_3V0_USIM: C125.2 J2.C1 U200.14@-4.4,8.65 V2.6 | length 13.8
  Top w0.152: v1(-9.24,9.937) -9.24,9.47 -9.398,9.47 -9.271,9.175 -9.271,8.537 -9.197,8.463 V2.6@-9.156,8.463 ; U200.14@-4.4,8.65 -4.318,8.732 v1(-4.318,10.16)
  Bottom w0.152: v1(-9.24,9.937) -4.635,9.937 -4.412,10.16 v1(-4.318,10.16) -3.52,10.958 -3.52,13.426 -4.16,14.066 -4.16,14.762 J2.C1
NET_STATUS: R7.2 U200.16 | length 8.9
  Top w0.152: R7.2 -5.207,1.742 v1(-5.207,1.397) ; v1(-2.523,7.747) -2.499,7.771 -2.499,8.351 U200.16
  Bottom w0.152: v1(-5.207,1.397) -5.207,5.08 -2.54,7.747 v1(-2.523,7.747)
NetC1_1: C1.1 Q1.2 R1.2 | length 2.2
  Top w0.152: R1.2 C1.1 4.547,3.437 Q1.2@4.699,3.589
NetC2_1: C2.1 Q2.2 R3.2 | length 3.6
  Top w0.152: C2.1 -0.254,2.846 0.519,3.619 1.715,3.619 2.159,3.175 R3.2
NetC3_1: C3.1 Q3.2 R5.2 | length 2.2
  Top w0.152: C3.1 R5.2 8.128,3.57 Q3.2
NetC7_1: C7.1 L1.1 U1.2 | length 9.2
  Bottom w0.15: C7.1@3.937,17.076 1.974,17.076 1.397,17.653 1.397,20.32 2.597,21.52 3.97,21.52 L1.1@4.445,21.995
NetC7_2: C7.2 U1.6 | length 1.4
  Bottom w0.15: C7.2 4.84,17.849 5.019,17.67 U1.6
NetC8_1: C8.1 R13.2 R14.1 U1.4 | length 3.7
  Bottom w0.2: U1.4 7.064,17.305 10.513,17.305 R14.1
NetD1_2: D1.2 R9.2 | length 1.1
  Top w0.152: D1.2 -13.311,4.385 R9.2
NetD2_2: D2.2 R10.2 | length 1.1
  Top w0.152: D2.2 -13.365,7.371 R10.2
NetQ4_2: Q4.2 R7.1 R8.2 | length 2.4
  Top w0.152: R8.2 R7.1 -5.334,2.769 -5.334,3.301 -5.336,3.303 -5.336,3.39 -5.564,3.619 Q4.2
NetQ4_3: Q4.3 R9.1 | length 5.1
  Top w0.152: R9.1 -12.153,4.127 Q4.3
NetQ5_2: Q5.2 R21.2 R22.1 | length 2.4
  Top w0.152: R21.2 R22.1 -2.413,2.997 -2.413,3.39 -2.184,3.619 Q5.2
NetQ5_3: Q5.3 R10.1 | length 10.7
  Top w0.152: R10.1 -11.889,7.556 -11.303,6.97 -11.303,5.715 -10.922,5.334 -6.486,5.334 -6.485,5.333 -5.707,5.333 ; Q5.3 -5,5.334 -5.706,5.334 ; -5.707,5.333 -5.706,5.334
  Top w0.3: R10.1 R10.1@-12.264,7.54
NetQ6_1: Q6.1 R23.1 | length 2
  Bottom w0.2: Q6.1@9.779,21.844 9.779,21.569 10.029,21.319 10.029,21.206 10.546,20.688 R23.1
PCM_CLK: 
PWR_KEY: R11.1 U200.7 | length 1.9
  Top w0.152: R11.1 -9.315,18.459 -8.984,18.459 -8.025,17.5 U200.7
RESET: U200.15
RX: D4.1 J1.2 R16.1 | length 3
  Bottom w0.152: R16.1@9.72,12.163 9.747,12.19 10.568,12.19 J1.2
RXD: Q2.1 R16.2 | length 14.3
  Top w0.152: Q2.1@1.281,4.606 1.46,4.427 v1(1.905,4.427)
  Bottom w0.152: v1(1.905,4.427) 2.903,3.429 4.826,3.429 6.35,4.953 6.35,9.017 8.596,11.263 R16.2
STATUS: R22.2 U200.25 | length 22.7
  Top w0.152: v1(-2.794,1.397) -2.794,1.716 R22.2 ; v1(6.913,8.835) 6.913,10.74 6.223,11.43 6.223,12.613 6.437,12.827 7.627,12.827 U200.25@7.9,13.1
  Bottom w0.152: v1(-2.794,1.397) -0.635,3.556 1.524,3.556 2.363,2.717 5.638,2.717 6.913,3.992 v1(6.913,8.835)
TX: D5.1 J1.3 R15.1 | length 3.5
  Bottom w0.15: R15.1 11.997,14.108 12.619,14.73 J1.3
TXD: Q1.3 R2.1 R15.2 | length 13
  Top w0.15: Q1.3 3.275,3.955 v1(3.81,3.955)
  Bottom w0.15: v1(3.81,3.955) 4.717,3.955 5.969,5.207 5.969,9.271 7.816,11.118 R2.1 R15.2@9.525,13.266
U1_DET: R17.1 U200.79 | length 8.6
  Top w0.152: v1(-4.191,13.081) -4.168,13.081 -3.556,13.693 -3.556,14.176 -3.232,14.5 U200.79@-3.2,14.5
  Bottom w0.152: R17.1 -8.89,15.182 -8.89,14.605 -6.477,12.192 -5.08,12.192 v1(-4.191,13.081)
U2_CLK: J6.C3 U200.62 V4.6 | length 31
  Top w0.152: v1(-4,19.812) -3.945,19.867 -2.249,19.867 -1.669,20.447 1.685,20.447 3.683,18.449 3.683,17.272 4.343,16.612 4.688,16.612 U200.62@5,16.3 ; U200.62@5,16.256 8.21,16.256 9.144,15.322 9.144,11.919 7.874,10.649 7.874,8.636 8.489,8.021 8.847,8.021 V4.6
  Bottom w0.152: J6.C3 -8.923,17.435 -8.599,17.759 -7.308,19.05 -4.762,19.05 v1(-4,19.812)
U2_DATA: J6.C7 U200.64 V4.4 | length 30
  Top w0.152: v1(-2.032,21.707) -2.005,21.679 -1.687,21.679 -1.189,21.18 1.919,21.18 4.082,19.018 4.682,19.018 5.324,18.376 5.627,18.376 7.014,16.989 8.538,16.989 9.906,15.621 9.906,11.684 8.678,10.456 8.678,9.04 8.752,8.966 V4.4
  Bottom w0.152: J6.C7 -7.653,17.435 -6.419,18.669 -4.318,18.669 -2.667,20.32 -2.667,21.072 v1(-2.032,21.707)
U2_DET: R18.1 U200.77 | length 5.5
  Top w0.152: U200.77@-3.2,16.9 -3.05,16.9 -2.096,17.854 v1(-2.096,18.311)
  Bottom w0.152: v1(-2.096,18.311) -0.42,18.311 0.323,17.568 R18.1
U2_RST: J6.C2 U200.63 V4.5 | length 28.5
  Top w0.152: v1(-2.032,20.828) 1.764,20.828 4.064,18.528 4.064,18.034 4.315,17.783 4.717,17.783 5,17.5 5.324,17.176 6.319,17.176 6.858,16.637 8.382,16.637 9.525,15.494 9.525,11.801 8.255,10.531 8.255,8.773 8.488,8.54 8.589,8.54 8.828,8.54 V4.5
  Bottom w0.152: J6.C2 -6.383,17.435 -5.53,18.288 -4.1,18.288 -2.032,20.356 v1(-2.032,20.828)
U2_VDD: C20.2 J6.C1 U200.65 V4.3 | length 26.7
  Top w0.152: v1(-0.889,21.707) 1.788,21.707 3.595,19.9 5,19.9 5.246,19.9 5.969,19.177 5.969,18.669 7.268,17.37 8.665,17.37 10.287,15.748 10.287,8.966 V4.3
  Bottom w0.152: J6.C1 -3.843,17.943 -1.397,20.389 -1.397,21.154 -0.889,21.662 v1(-0.889,21.707)
UART2_RXD: Q2.3 R4.1 U200.17 | length 7
  Top w0.152: R4.1 -1.39,2.775 -1.39,3.081 -0.345,4.127 -0.409,4.191 -0.381,4.219 v1(-0.381,4.708) ; v1(-1.355,7.747) -1.355,8.395 U200.17
  Bottom w0.152: v1(-1.355,7.747) -0.381,6.773 v1(-0.381,4.708)
UART2_TXD: Q1.1 U200.18 | length 10.7
  Top w0.152: v1(-0.586,7.722) -0.299,8.009 -0.299,8.351 U200.18 ; v1(0.399,4.186) 0.381,4.204 0.381,5.059 0.656,5.334 1.134,5.334 1.135,5.333 1.534,5.333 1.914,4.953 3.379,4.953 3.697,4.635 Q1.1
  Bottom w0.152: v1(-0.586,7.722) -0.029,7.165 -0.029,5.1 0.399,4.672 v1@0.399,4.195
UART_DTR: Q3.3 R6.1 U200.19 | length 12.8
  Top w0.152: v1(0.194,7.687) 0.26,7.753 0.895,7.753 1.1,7.958 U200.19 ; R6.1 5.715,2.692 5.715,3.462 5.842,3.589 v1(5.842,3.683) 5.886,3.727 6.151,3.727 Q3.3
  Bottom w0.152: v1(0.194,7.687) 0.194,7.611 0.381,7.424 0.381,5.206 2.511,3.077 5.236,3.077 v1(5.842,3.683)
USB_BOOT: TP5.1 U200.82 | length 10
  Top w0.152: U200.82 v1(4.047,14.5)
  Bottom w0.152: TP5.1@3.556,6.708 2.54,7.724 2.54,11.811 2.793,12.064 3.301,12.064 3.556,12.319 3.556,14.009 v1@4.043,14.496
USB_DM: TP3.1 U200.60 | length 5.6
  Top w0.152: v1(4.191,13.502) 4.286,13.502 4.36,13.576 4.676,13.576 U200.60
  Bottom w0.152: TP3.1@3.556,9.682 4.844,10.97 4.844,12.849 v1(4.191,13.502)
USB_DP: TP2.1 U200.59 | length 2.8
  Top w0.152: v1(4.191,12.7) U200.59
  Bottom w0.152: TP2.1@3.556,11.169 3.857,11.169 3.857,11.246 4.191,11.58 v1(4.191,12.7)
USIM_CLK: J2.C3 U200.13 V2.4 | length 15.4
  Top w0.152: V2.4@-9.156,7.463 -8.704,7.463 -8.001,8.166 -8.001,10.799 U200.13 -7.751,11.049 v1(-1.778,11.049)
  Bottom w0.152: v1(-1.778,11.049) -1.71,11.049 -0.508,12.251 -0.508,13.335 0.403,14.246 0.403,14.532 J2.C3@0.822,14.951
USIM_DATA: J2.C7 U200.11 V2.3 | length 23.2
  Top w0.152: V2.3@-10.615,7.454 -10.506,7.454 -10.432,7.38 -10.432,6.876 v1(-10.414,6.858) ; U200.11 -7.601,12.801 -6.451,12.801 -5.842,12.192 -2.159,12.192 v1(-1.778,11.811)
  Bottom w0.152: v1(-10.414,6.858) -10.414,6.867 -10.668,7.121 -10.668,8.745 -10.015,9.398 -4.191,9.398 v1(-1.778,11.811) -0.867,12.722 -0.867,14.532 J2.C7@-0.443,14.956
USIM_RST: J2.C2 U200.12 V2.5 | length 15.5
  Top w0.152: V2.5@-9.156,7.963 -8.704,7.963 -8.509,8.158 -8.509,10.16 -8.763,10.414 -8.763,11.43 -8.492,11.701 -7.174,11.701 -6.683,12.192 ; U200.12 -7.689,12.211 -6.683,12.211 -6.683,11.808 -6.576,11.701 -3.029,11.701 v1(-2.993,11.666)
  Bottom w0.152: v1(-2.993,11.666) -1.905,12.754 J2.C2@-1.905,14.764
VBAT: C6.2 C8.2 C9.2 C10.2 C137.2 C138.2 L1.2 R13.1 R20.2 U6.3 U200.42 U200.43 V3.1 | length 27.6
  Top w0.3: U200.42 U200.42@-2.2,26.475 ; v1(-0.635,27.686) C138.2@-0.237,27.686 ; -0.326,27.305 -0.326,27.597 C138.2@-0.237,27.686 ; v1(1.27,27.559) 0.842,27.987 C138.2 ; C138.2@-0.237,27.686 0.064,27.987 C138.2 ; C138.2@-0.237,27.686 0.08,27.686 C138.2
  Bottom w0.3: v1(-3.048,27.559) -0.889,27.559 ; C9.2@3.01,27.051 C9.2@3.106,26.955 ; L1.2@3.012,24.914 3.312,24.614 L1.2 ; L1.2@3.429,24.93 3.154,24.655 2.811,24.655 2.032,23.876 2.032,21.844 0.889,20.701 0.889,17.526 2.159,16.256 7.175,16.256 U6.3@7.366,16.065 ; U6.3 7.511,15.839 7.511,15.601 7.686,15.425 C10.2 9.652,15.43 R13.1 C8.2
  other v1: -3.048,28.321 -0.635,28.321 1.27,28.321
VBUCK2_1V8: C1.2 C2.2 C3.2 C301.2 Q7.1 Q8.1 Q9.1 R1.1 R3.1 R4.2 R5.1 R6.2 R24.1 R27.2 R29.1 U200.24 | length 34.6
  Top w0.152: Q9.1 -3.741,5.884 R29.1 -2.217,5.307 -0.027,5.307 0.415,5.749 0.572,5.749 0.708,5.884 R24.1 2.101,5.307 3.048,5.307 3.564,5.823 Q7.1 4.903,5.884 R27.2 C301.2 ; R4.2 C2.2 R3.1 R1.1 C1.2 R6.2 C3.2 R5.1 8.327,1.966 8.47,1.966 8.89,2.386 8.89,5.207 8.409,5.688 7.054,5.688 C301.2 ; v1(7.493,6.096) 7.48,6.083 7.057,6.083 C301.2 ; v1@7.493,8.255 7.493,11.049 7.9,11.456 U200.24 7.792,12 U200.24@7.493,11.701
  Bottom w0.152: v1(7.493,6.096) v1(7.493,8.128)
VBUS: TP4.1 U200.61 | length 9
  Top w0.152: v1(4.191,15.24) 4.86,15.24 U200.61
  Bottom w0.152: TP4.1@3.556,8.195 5.207,9.846 5.207,14.224 v1(4.191,15.24)
VIN: J1.5 Q6.3 | length 6.3
  Bottom w0.8: Q6.3@8.879,23.594 8.879,23.495 10.414,23.495 11.049,22.86 11.049,21.461 J1.5
VIN_3V3: C11.2 D1.1 D2.1 R2.2 R25.1 R26.1 R28.2 U6.2 | length 40.1
  Top w0.2: D2.1 -11.911,6.486 -11.911,5.2 -11.711,5 -11.681,5 v1@-11.497,4.816 ; v1(-6.985,6.223) -6.424,6.784 R26.1 ; v1(-1.905,7.239) -1.905,6.911 R25.1 ; R28.2 2.66,6.904 2.967,6.904 4.216,8.153 5.055,8.153 5.387,7.821 5.387,7.66 v1(5.444,7.603)
  Bottom w0.152: -2.159,8.509 -1.905,8.255 -1.651,8.509
  Bottom w0.2: v1(-11.43,4.653) -8.555,4.653 v1(-6.985,6.223) -4.826,6.223 -2.54,8.509 -1.905,8.509 ; v1(-1.905,7.239) -1.905,8.509 ; U6.2 6.416,13.059 6.702,12.773 6.716,12.773 C11.2 R2.2 6.916,10.853 5.399,9.336 5.399,7.782 5.488,7.692 5.516,7.692 5.444,7.62 5.444,5.212 4.779,4.547 2.692,4.547 0.889,6.35 0.889,7.874 0.254,8.509 -1.905,8.509
VIN_5V: C4.2 C5.2 Q6.2 R12.1 U1.3 V1.1 | length 13.2
  Bottom w0.2: V1.1 8.582,25.581 9.779,24.384 R12.1
  Bottom w0.5: U1.3 7.166,20.135 C5.2 9.175,20.135 C4.2 8.971,20.231 8.871,20.331 8.871,20.631 8.033,21.469 7.979,21.469 7.879,21.569 V1.1@7.879,25.781
VIN_EN: J1.6 R12.2 U1.5 | length 13.1
  Top w0.15: v1(7.747,18.034) 7.842,18.034 8.096,17.78 10.922,17.78 11.303,18.161 11.303,20.953 J1.6
  Bottom w0.15: U1.5 5.969,17.831 6.498,18.36 7.421,18.36 v1(7.747,18.034) ; J1.6 R12.2
VIO1: Q7.2 R27.1 U200.50 | length 18.6
  Top w0.15: U200.50@-5,16.3 -4.783,16.083 -2.875,16.083 -2.032,15.24 -2.032,15.227 -2.025,15.22 -2.025,13.81 -0.381,12.166 -0.381,11.303 0.127,10.795 1.638,10.795 2.152,10.28 2.152,9.151 2.667,8.636 5.207,8.636 5.969,7.874 5.969,6.911 R27.1 5.803,6.823 Q7.2
VIO2: Q8.2 R24.2 U200.51 | length 15.1
  Top w0.15: U200.51@-5,15.1 -4.675,15.425 -4.514,15.425 -4.349,15.59 -2.89,15.59 -2.375,15.075 -2.375,13.665 -0.762,12.052 -0.762,10.922 -0.254,10.414 1.524,10.414 1.75,10.188 1.75,7.01 R24.2 1.485,6.823 Q8.2
VIO3: Q9.2 R29.2 U200.52 | length 13.3
  Top w0.15: U200.52@-4.515,13.9 -5,13.9 -5,13.148 -4.408,12.556 -1.761,12.556 -1.143,11.938 -1.143,10.795 -1.524,10.414 -2.667,10.414 -3.048,10.033 -3.048,7.038 R29.2 -3.764,6.784 Q9.2
pads on no net: J2. J2.C6 J6. J6.C6 U200.1@0,8.65 U200.1@0,26.35 U200.1@1.1,8.65 U200.1@3.3,26.35 U200.1@4.4,26.35 U200.1@7.9,12 U200.1@7.9,13.1 U200.1@7.9,15.3 U200.1@7.9,23 U200.1@7.9,24.1 U200.1@-1.1,8.65 U200.1@-1.1,26.35 U200.1@-2.2,8.65 U200.1@-2.2,26.35 U200.1@-3.3,26.35 U200.1@-4.4,8.65 U200.1@-5.5,8.65 U200.1@-7.9,10.9 U200.1@-7.9,12 U200.1@-7.9,13.1 U200.1@-7.9,14.2 U200.1@-7.9,17.5 U200.1@-7.9,23 U200.1@-7.9,24.1 U200.2 U200.3 U200.4 U200.5 U200.6 U200.8 U200.9 U200.14@2.2,8.65 U200.14@3.3,8.65 U200.14@4.4,8.65 U200.14@5.5,8.65 U200.14@5.5,26.35 U200.14@7.9,10.9 U200.14@7.9,14.2 U200.14@7.9,16.4 U200.14@7.9,17.5 U200.14@7.9,18.6 U200.14@7.9,19.7 U200.14@7.9,20.8 U200.14@7.9,21.9 U200.14@-3.3,8.65 U200.14@-4.4,26.35 U200.14@-5.5,26.35 U200.20 U200.21 U200.22 U200.23 U200.26 U200.28 U200.29 U200.31 U200.32 U200.33 U200.40@2.2,26.35 U200.41@1.1,26.35 U200.44 U200.45@0,23.45 U200.45@3.2,14.5 U200.45@3.2,21.7 U200.45@5,11.5 U200.45@5,12.7 U200.45@5,13.9 U200.45@5,15.1 U200.45@5,16.3 U200.45@5,17.5 U200.45@5,18.7 U200.45@5,19.9 U200.45@5,21.1 U200.45@5,22.3 U200.45@5,23.5 U200.45@-1.2,23.45 U200.45@-2.4,23.45 U200.45@-3.2,14.5 U200.45@-3.2,16.9 U200.45@-3.2,21.7 U200.45@-3.6,11.45 U200.45@-3.6,23.45 U200.45@-5,11.5 U200.45@-5,12.7 U200.45@-5,13.9 U200.45@-5,15.1 U200.45@-5,16.3 U200.45@-5,17.5 U200.45@-5,18.7 U200.45@-5,19.9 U200.45@-5,21.1 U200.45@-5,22.3 U200.45@-5,23.5 U200.49 U200.53 U200.54 U200.55 U200.56 U200.57 U200.58 U200.66 U200.67 U200.68 U200.69 U200.70@0,11.45 U200.70@0,13.45 U200.70@2.4,11.45 U200.70@2.4,23.45 U200.70@3.2,16.9 U200.70@3.2,19.3 U200.70@-3.2,19.3 U200.71@1.2,11.45 U200.71@1.2,13.45 U200.71@1.2,23.45 U200.71@3.2,13.3 U200.71@3.2,15.7 U200.71@3.2,18.1 U200.71@3.2,20.5 U200.71@-1.2,11.45 U200.71@-1.2,13.45 U200.71@-3.2,13.3 U200.71@-3.2,15.7 U200.71@-3.2,18.1 U200.71@-3.2,20.5 U200.72@3.6,11.45 U200.72@3.6,23.45 U200.72@-2.4,11.45 U200.74 U200.75 U200.76 U200.78 U200.80 U200.81 U200.83 U200.84 U200.85 U200.86 U200.87 U200.89@0.9,15.7 U200.89@0.9,17.5 U200.89@0.9,19.3 U200.89@-0.9,15.7 U200.89@-0.9,17.5 U200.89@-0.9,19.3 U200.96 U200.97 U200.98 U200.99 U200.100 U200.101 U200.102 U200.103 U200.104 U200.105 U200.106 U200.107 U200.108 U200.109 V2.1 V4.1

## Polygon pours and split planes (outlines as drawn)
BAT on Bottom "NONET_L-01_P-001" (solid, remove dead copper, pour order 8): -11.811,24.892 -10.795,23.876 -10.795,20.574 -11.557,19.812 -11.557,23.241 -12.192,23.876 -12.827,23.876 -12.827,24.892
GND on Bottom "NONET_L-01_P-001" (solid, remove dead copper, pour order 9): 14.605,32.639 14.605,-0.254 -14.478,-0.254 -14.478,32.639
VBAT on Bottom "NONET_L-01_P-001" (solid, remove dead copper, pour order 7): -11.049,27.178 -11.557,26.67 -11.557,25.908 -12.827,25.908 -12.827,27.305 -11.557,28.575 2.921,28.575 3.302,28.194 3.302,24.13 2.413,24.13 2.413,26.564 1.799,27.178 -4.191,27.178
NetC7_1 on Bottom "NONET_L-01_P-001" (solid, remove dead copper, pour order 6): 6.35,19.304 6.35,22.098 4.826,22.098 4.826,21.463 5.588,20.701 5.588,19.304
VBAT on Top "NONET_L-01_P-001" (solid, remove dead copper, pour order 11): 0.254,28.575 0.635,28.956 0.635,30.988 0.889,31.242 1.651,31.242 1.905,30.988 1.905,27.686 1.419,27.2 1.314,27.305 0.254,27.305
GND on Top "NONET_L-01_P-001" (solid, remove dead copper, pour order 5): 14.605,32.639 14.605,-0.254 -14.478,-0.254 -14.478,32.639
VBAT on Top "Top-VBAT" (solid, remove dead copper, pour order 4): -3.7,24.9 -2.9,24.9 -2.9,27 -2.6,27 -2.6,24.9 -1.8,24.9 -1.8,27 -1.6,27.2 1.419,27.2 1.651,27.432 1.651,28.448 1.397,28.702 -3.302,28.702 -3.7,28.304

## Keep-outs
Top:
  region: 8.2,31 8.2,29 10.2,29 10.2,31 8.2,31
Keep-Out Layer:
  the board outline again, w0.15

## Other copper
Top:
  pour cut-out: 8.6,23.525 8.687,23.525 ccw(c8.687,24.638) 9.8,24.638 ccw(c9.546,24.638) 9.546,24.892 9.525,24.892
  pour cut-out: -4.2,16.95 -3.996,16.95 -3.81,16.764
  pour cut-out: 8.653,1.242 -2.479,1.242 -2.794,1.557
  pour cut-out: 8.65,13.725 8.881,13.725 9.017,13.589
  pour cut-out: 6.25,13.725 5.724,13.725 5.588,13.589
  pour cut-out: 14.351,16.129 11.7,16.129 11.7,8.509 14.351,8.509
  pour cut-out: -11.303,18.669 -11.303,8.001 -14.224,8.001 -14.224,18.669
  pour cut-out: 8.6,28.796 8.6,24.638 9.8,24.638 9.8,28.796
Bottom:
  pour cut-out: -13.103,25.691 -13.103,25.109 -11.303,25.109 -11.303,25.691
  pour cut-out: 6.477,24.13 6.477,22.098 2.159,22.098 2.159,24.13
  pour cut-out: -7.366,16.256 -7.366,15.748 0.508,15.748 0.508,16.256
  pour cut-out: 14.351,16.129 11.7,16.129 11.7,8.509 14.351,8.509
  pour cut-out: -11.557,18.669 -11.557,8.001 -14.224,8.001 -14.224,18.669

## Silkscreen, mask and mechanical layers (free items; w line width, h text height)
Silkscreen Top:
  text "LTE" at 12.446,28.448 h2 r90
  text "GND" at -11.206,21.907 h1.3
  text "EN" at 9.642,21.891 h1.5
  text "GND" at -11.206,19.337 h1.3
  text "VIN" at 9.17,19.321 h1.5
  text "GND" at 8.831,16.827 h1.3
  text "VBAT" at -11.206,16.813 h1
  text "PIN50" at -16.74,14.478 h1
  text "IO1" at -11.206,14.347 h1.3
  text "TX" at 9.618,14.329 h1.5
  text "IO2" at -11.206,12.234 h1.3
  text "RX" at 9.538,12.216 h1.5
  text "PIN51" at -16.638,11.938 h1
  text "IO3" at -11.206,10.122 h1.3
  text "DTR" at 8.649,10.104 h1.5
  text "PIN52" at -16.739,9.398 h1
  text "STATUS" at -11.206,6.159 h1
  text "NET" at -11.206,4.953 h1
  text "TX/RX:" at 8.863,2.908 h1.3
  text "LEVEL:3.3V" at 8.763,1.905 h1
  text "3.4V-4.5V" at -7.874,0.224 h1.8
  text "DC5V-16V" at 5.461,0.224 h1.8
  text "VBAT:" at -12.827,0.202 h1.8
  text "VIN:" at 2.159,0.202 h1.8
  text "DX-PJ31-V1.2/黑油白字/无铅喷锡/1.6/2L/32*28mm" at -14.605,-2.032 h1.5
Silkscreen Bottom:
  lines w0.15: 5.127,29.151 5.704,29.151 5.704,30.969 6.212,30.969 6.212,29.147 6.735,29.147 5.933,28.345 5.127,29.151 ; 7.351,5.27 8.152,6.072 8.958,5.266 8.382,5.266 8.382,3.448 7.874,3.448 7.874,5.27 7.351,5.27
  lines w0.2: 4.815,28.448 4.815,31.623 8.509,31.623 8.509,26.67 6.593,26.67 4.815,28.448 ; 5.577,2.794 9.271,2.794 9.271,5.969 7.493,7.747 5.577,7.747 5.577,2.794
  text "SIM1" at 4.445,31.75 h1.8 r90
  text "NANO SIM" at 7.99,31.369 h1 r90
  text "R" at 13.462,30.099 h1
  text "T" at 13.407,28.575 h1
  text "G" at 13.493,26.924 h1
  text "P" at 5.237,11.049 h1
  text "M" at 5.359,9.525 h1
  text "V" at 5.334,8.001 h1
  text "B" at 5.232,6.477 h1
  text "G" at 5.341,5.207 h1
  text "NANO SIM" at 6.096,3.048 h1 r270
  text "SIM0" at 3.292,0.635 h1.8 r270
  text "M" at 8.255,0.508 h3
